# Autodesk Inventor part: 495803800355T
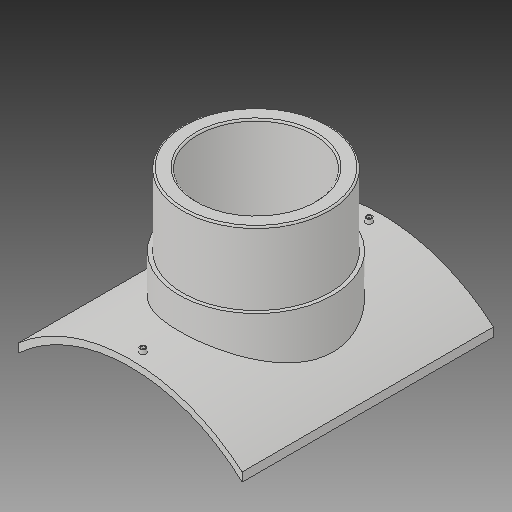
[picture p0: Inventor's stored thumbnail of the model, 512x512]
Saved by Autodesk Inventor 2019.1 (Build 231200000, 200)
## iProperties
Created: 2017-10
Part Number: 495803800355T
Material: Generic
Description: PLASSON BRANCH SADDLE  800x355
Document SubType Name: Modeling
Designer: KIM
Mass: 2754.05 g
Surface Area: 3037.44 cm^2
Volume: 2754.05 cm^3
Density: 1 g/cm^3
Appearance: Default
Author: KIM
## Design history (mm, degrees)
derived "495803.ipt"
feature "Solid1::495803.ipt"
tag "TaggingFeature1"
body "Solid1"
other parameters: "d1" = 16, "d2" = 543, "d4" = 0, "d12" = 425.6, "d13" = 14, "d14" = 274.5, "d16" = 5 deg, "d18" = 4, "d19" = 14, "d20" = 0, "d21" = 3, "d22" = 0, "d23" = 668, "d24" = 372.75, "d25" = 16, "d26" = 284, "d28" = 0, "d29" = 9.6, "d31" = 0, "d32" = 126, "d33" = 0, "d34" = 8, "d36" = 355, "d37" = 176.4, "d38" = 0, "d39" = 4, "d_1" = 355, "B_" = 543, "H_" = 252, "x_" = 16, "D_" = 16
